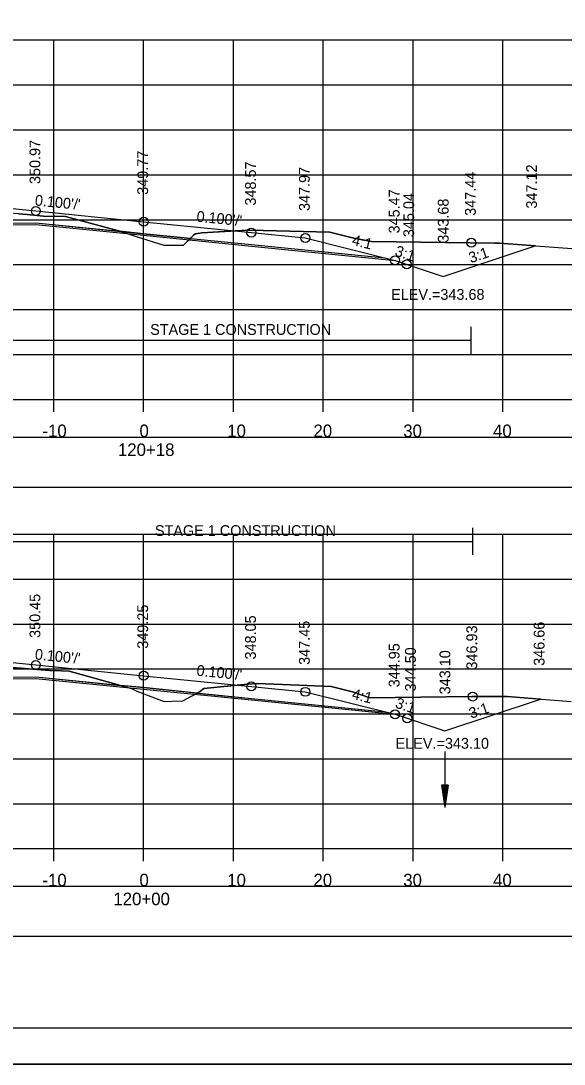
# Model space of a CAD drawing. Extents: x 1376273 to 1384221, y 378927 to 384592.
# Drawn here: x 1377044.1 to 1377104.6, y 380325.2 to 380441.3 of the extents above; entities that cross this region are included whole.
import ezdxf

# ---------------------------------------------------------------- set-up
doc = ezdxf.new("R2010")
doc.units = 0
for name, color, linetype in [('R_Alt Surface', 7, 'Continuous'), ('R_Axis', 7, 'Continuous'), ('R_Axis Annot', 7, 'Continuous'), ('R_Border', 7, 'Continuous'), ('R_Border Notes', 7, 'Continuous'), ('R_Dimension', 7, 'Continuous'), ('R_Exist Surface', 7, 'Continuous'), ('R_Fin Surface', 7, 'Continuous'), ('R_Grid', 7, 'Continuous'), ('R_No Plot', 7, 'Continuous'), ('R_Water', 7, 'Continuous'), ('R_Xsect Elev', 7, 'Continuous'), ('R_Xsect Slope', 7, 'Continuous'), ('T_Detection Zones', 7, 'Continuous')]:
    doc.layers.add(name, color=color, linetype=linetype)

msp = doc.modelspace()

# ---------------------------------------------------------------- linework, layer by layer
at = {"layer": 'R_Alt Surface'}
for points in [[(1377031.48, 380418.66), (1377045.77, 380418.8), (1377057.77, 380417.6), (1377069.77, 380416.4), (1377084.63, 380414.91)], [(1377031.48, 380368.13), (1377045.77, 380368.28), (1377057.77, 380367.08), (1377069.77, 380365.88), (1377084.63, 380364.39)]]:
    msp.add_lwpolyline(points, dxfattribs=at)
at = {"layer": 'R_Axis'}
for p, q in [((1376907.77, 380399.16), (1377207.77, 380399.16)), ((1377047.77, 380397.76), (1377047.77, 380399.16)), ((1377057.77, 380397.76), (1377057.77, 380399.16)), ((1377067.77, 380397.76), (1377067.77, 380399.16)), ((1377077.77, 380397.76), (1377077.77, 380399.16)), ((1377087.77, 380397.76), (1377087.77, 380399.16)), ((1377097.77, 380397.76), (1377097.77, 380399.16)), ((1376907.77, 380349.16), (1377207.77, 380349.16)), ((1377047.77, 380347.76), (1377047.77, 380349.16)), ((1377057.77, 380347.76), (1377057.77, 380349.16)), ((1377067.77, 380347.76), (1377067.77, 380349.16)), ((1377077.77, 380347.76), (1377077.77, 380349.16)), ((1377087.77, 380347.76), (1377087.77, 380349.16)), ((1377097.77, 380347.76), (1377097.77, 380349.16))]:
    msp.add_line(p, q, dxfattribs=at)
at = {"layer": 'R_Axis Annot'}
for points in [[(1376907.2, 380389.4), (1377209.01, 380389.4), (1377209.01, 380394.92), (1376907.2, 380394.92)], [(1376907.2, 380339.4), (1377209.01, 380339.4), (1377209.01, 380344.93), (1376907.2, 380344.93)]]:
    msp.add_lwpolyline(points, close=True, dxfattribs=at)
at = {"layer": 'R_Border'}
msp.add_line((1377215.95, 380329.16), (1376899.77, 380329.16), dxfattribs=at)
at = {"layer": 'R_Dimension'}
for p, q in [((1377094.26, 380404.24), (1377094.26, 380407.24)), ((1377000.91, 380405.74), (1377094.26, 380405.74)), ((1377094.41, 380381.86), (1377094.41, 380384.86)), ((1377001.54, 380383.36), (1377094.41, 380383.36))]:
    msp.add_line(p, q, dxfattribs=at)
at = {"layer": 'R_Exist Surface'}
for points in [[(1377043.83, 380419.81), (1377044.82, 380419.72), (1377047.01, 380419.53), (1377047.87, 380419.54), (1377049.06, 380419.53), (1377054.14, 380418.14), (1377055.82, 380417.67), (1377057.06, 380417.24), (1377060.04, 380416.31), (1377061.51, 380416.33), (1377062.23, 380416.31), (1377063.35, 380417.47), (1377063.56, 380417.6), (1377064.24, 380417.68), (1377069.39, 380418), (1377069.54, 380418.01), (1377069.59, 380418.01), (1377078.52, 380417.78), (1377081.16, 380417.1), (1377083.13, 380416.75), (1377096.88, 380416.56), (1377097.08, 380416.56), (1377097.41, 380416.53), (1377122.09, 380414.74)], [(1377038.09, 380369.71), (1377044.15, 380369.23), (1377045.87, 380369.08), (1377047.3, 380368.97), (1377048.63, 380368.95), (1377049.48, 380368.92), (1377055.07, 380367.37), (1377056.43, 380366.99), (1377057.03, 380366.7), (1377060.05, 380365.54), (1377060.96, 380365.59), (1377062.13, 380365.6), (1377063.99, 380366.61), (1377064.47, 380367), (1377068.95, 380367.43), (1377070.36, 380367.53), (1377073.25, 380367.44), (1377078.66, 380367.21), (1377081.04, 380366.61), (1377082.96, 380365.95), (1377094.33, 380366.09), (1377098.25, 380366.08), (1377105.38, 380365.55)]]:
    msp.add_lwpolyline(points, dxfattribs=at)
at = {"layer": 'R_Fin Surface'}
for points in [[(1377000.91, 380418.81), (1377029.77, 380418.23), (1377030.77, 380418.48), (1377039.77, 380420.73), (1377045.77, 380420.13), (1377057.77, 380418.93), (1377069.77, 380417.73), (1377075.77, 380417.13), (1377085.77, 380414.63), (1377091.13, 380412.84), (1377101.35, 380416.25)], [(1377001.54, 380368.27), (1377029.77, 380367.71), (1377030.77, 380367.96), (1377039.77, 380370.21), (1377045.77, 380369.61), (1377057.77, 380368.41), (1377069.77, 380367.21), (1377075.77, 380366.61), (1377085.77, 380364.11), (1377091.32, 380362.26), (1377101.96, 380365.8)]]:
    msp.add_lwpolyline(points, dxfattribs=at)
at = {"layer": 'R_Grid'}
for p, q in [((1376907.77, 380439.16), (1377207.77, 380439.16)), ((1376907.77, 380439.16), (1377207.77, 380439.16)), ((1377047.77, 380399.16), (1377047.77, 380439.16)), ((1377047.77, 380399.16), (1377047.77, 380439.16)), ((1377057.77, 380399.16), (1377057.77, 380439.16)), ((1377057.77, 380399.16), (1377057.77, 380439.16)), ((1377067.77, 380399.16), (1377067.77, 380439.16)), ((1377067.77, 380399.16), (1377067.77, 380439.16)), ((1377077.77, 380399.16), (1377077.77, 380439.16)), ((1377077.77, 380399.16), (1377077.77, 380439.16)), ((1377087.77, 380399.16), (1377087.77, 380439.16)), ((1377087.77, 380399.16), (1377087.77, 380439.16)), ((1377097.77, 380399.16), (1377097.77, 380439.16)), ((1377097.77, 380399.16), (1377097.77, 380439.16)), ((1376907.77, 380434.16), (1377207.77, 380434.16)), ((1376907.77, 380434.16), (1377207.77, 380434.16)), ((1376907.77, 380429.16), (1377207.77, 380429.16)), ((1376907.77, 380429.16), (1377207.77, 380429.16)), ((1376907.77, 380424.16), (1377207.77, 380424.16)), ((1376907.77, 380424.16), (1377207.77, 380424.16)), ((1376907.77, 380419.16), (1377207.77, 380419.16)), ((1376907.77, 380419.16), (1377207.77, 380419.16)), ((1376907.77, 380414.16), (1377207.77, 380414.16)), ((1376907.77, 380414.16), (1377207.77, 380414.16)), ((1376907.77, 380409.16), (1377207.77, 380409.16)), ((1376907.77, 380409.16), (1377207.77, 380409.16)), ((1376907.77, 380404.16), (1377207.77, 380404.16)), ((1376907.77, 380404.16), (1377207.77, 380404.16)), ((1376907.77, 380399.16), (1377207.77, 380399.16)), ((1376907.77, 380399.16), (1377207.77, 380399.16)), ((1376907.77, 380384.16), (1377207.77, 380384.16)), ((1376907.77, 380384.16), (1377207.77, 380384.16)), ((1377047.77, 380349.16), (1377047.77, 380384.16)), ((1377047.77, 380349.16), (1377047.77, 380384.16)), ((1377057.77, 380349.16), (1377057.77, 380384.16)), ((1377057.77, 380349.16), (1377057.77, 380384.16)), ((1377067.77, 380349.16), (1377067.77, 380384.16)), ((1377067.77, 380349.16), (1377067.77, 380384.16)), ((1377077.77, 380349.16), (1377077.77, 380384.16)), ((1377077.77, 380349.16), (1377077.77, 380384.16)), ((1377087.77, 380349.16), (1377087.77, 380384.16)), ((1377087.77, 380349.16), (1377087.77, 380384.16)), ((1377097.77, 380349.16), (1377097.77, 380384.16)), ((1377097.77, 380349.16), (1377097.77, 380384.16)), ((1376907.77, 380379.16), (1377207.77, 380379.16)), ((1376907.77, 380379.16), (1377207.77, 380379.16)), ((1376907.77, 380374.16), (1377207.77, 380374.16)), ((1376907.77, 380374.16), (1377207.77, 380374.16)), ((1376907.77, 380369.16), (1377207.77, 380369.16)), ((1376907.77, 380369.16), (1377207.77, 380369.16)), ((1376907.77, 380364.16), (1377207.77, 380364.16)), ((1376907.77, 380364.16), (1377207.77, 380364.16)), ((1376907.77, 380359.16), (1377207.77, 380359.16)), ((1376907.77, 380359.16), (1377207.77, 380359.16)), ((1376907.77, 380354.16), (1377207.77, 380354.16)), ((1376907.77, 380354.16), (1377207.77, 380354.16)), ((1376907.77, 380349.16), (1377207.77, 380349.16)), ((1376907.77, 380349.16), (1377207.77, 380349.16))]:
    msp.add_line(p, q, dxfattribs=at)
at = {"layer": 'R_No Plot'}
msp.add_line((1376887.37, 380325.18), (1377220.7, 380325.18), dxfattribs=at)
for points in [[(1376887.36, 380538.51), (1377220.7, 380538.51), (1377220.7, 380325.17), (1376887.36, 380325.17)], [(1377133.69, 380534.62), (1377133.69, 380524.74), (1377169.42, 380524.74), (1377169.42, 380521.82), (1377192.62, 380521.82), (1377192.62, 380497.48), (1377215.95, 380497.48), (1377215.95, 380329.16), (1376899.77, 380329.16), (1376899.77, 380534.62)]]:
    msp.add_lwpolyline(points, close=True, dxfattribs=at)
for points in [[(1377030.77, 380418.48), (1377045.77, 380418.63), (1377057.77, 380417.43), (1377069.77, 380416.23), (1377085.77, 380414.63)], [(1377030.77, 380367.96), (1377045.77, 380368.11), (1377057.77, 380366.91), (1377069.77, 380365.71), (1377085.77, 380364.11)]]:
    msp.add_lwpolyline(points, dxfattribs=at)
for centre in [(1377045.77, 380420.13), (1377045.77, 380420.13), (1377057.77, 380418.93), (1377057.77, 380418.93), (1377069.77, 380417.73), (1377069.77, 380417.73), (1377075.77, 380417.13), (1377075.77, 380417.13), (1377094.26, 380416.59), (1377094.26, 380416.59), (1377085.77, 380414.63), (1377085.77, 380414.63), (1377087.07, 380414.2), (1377087.07, 380414.2), (1377087.07, 380414.2), (1377087.07, 380414.2), (1377045.77, 380369.61), (1377045.77, 380369.61), (1377057.77, 380368.41), (1377057.77, 380368.41), (1377069.77, 380367.21), (1377069.77, 380367.21), (1377075.77, 380366.61), (1377075.77, 380366.61), (1377094.41, 380366.09), (1377094.41, 380366.09), (1377085.77, 380364.11), (1377085.77, 380364.11), (1377087.12, 380363.66), (1377087.12, 380363.66), (1377087.12, 380363.66), (1377087.12, 380363.66)]:
    msp.add_circle(centre, 0.5, dxfattribs=at)
at = {"layer": 'R_Water'}
for p, q in [((1377091.32, 380359.97), (1377091.32, 380353.72)), ((1377090.94, 380356.22), (1377091.32, 380353.72)), ((1377091.69, 380356.22), (1377090.94, 380356.22)), ((1377091, 380356.22), (1377091.32, 380354.14)), ((1377091.07, 380356.22), (1377091.32, 380354.57)), ((1377091.13, 380356.22), (1377091.32, 380354.99)), ((1377091.19, 380356.22), (1377091.32, 380355.41)), ((1377091.26, 380356.22), (1377091.32, 380355.83)), ((1377091.69, 380356.22), (1377091.32, 380353.72)), ((1377091.44, 380356.22), (1377091.32, 380355.41)), ((1377091.56, 380356.22), (1377091.32, 380354.57)), ((1377091.63, 380356.22), (1377091.32, 380354.14)), ((1377091.5, 380356.22), (1377091.32, 380354.99)), ((1377091.37, 380356.22), (1377091.32, 380355.83))]:
    msp.add_line(p, q, dxfattribs=at)
at = {"layer": 'T_Detection Zones'}
for p, q in [((1377042.83, 380418.77), (1377045.77, 380418.8)), ((1377045.77, 380418.8), (1377055.12, 380417.87)), ((1377057.77, 380417.6), (1377055.12, 380417.87)), ((1377062.98, 380417.08), (1377057.77, 380417.6)), ((1377062.98, 380417.08), (1377069.77, 380416.4)), ((1377069.77, 380416.4), (1377084.63, 380414.91)), ((1377043.15, 380368.25), (1377045.77, 380368.28)), ((1377045.77, 380368.28), (1377055.21, 380367.33)), ((1377057.77, 380367.08), (1377055.21, 380367.33)), ((1377063.75, 380366.48), (1377057.77, 380367.08)), ((1377063.75, 380366.48), (1377069.77, 380365.88)), ((1377069.77, 380365.88), (1377084.63, 380364.39))]:
    msp.add_line(p, q, dxfattribs=at)
for points in [[(1377055.12, 380417.87), (1377054.14, 380418.14), (1377049.06, 380419.53), (1377047.87, 380419.54), (1377047.01, 380419.53), (1377044.82, 380419.72), (1377043.83, 380419.81), (1377042.83, 380419.89)], [(1377101.35, 380416.25), (1377097.41, 380416.53), (1377097.08, 380416.56), (1377096.88, 380416.56), (1377083.13, 380416.75), (1377081.16, 380417.1), (1377078.52, 380417.78), (1377069.59, 380418.01), (1377069.54, 380418.01), (1377069.39, 380418), (1377067.95, 380417.91), (1377064.24, 380417.68), (1377063.56, 380417.6), (1377063.35, 380417.47), (1377062.98, 380417.08)], [(1377055.12, 380417.87), (1377055.82, 380417.67), (1377057.06, 380417.24), (1377060.04, 380416.31), (1377061.51, 380416.33), (1377062.23, 380416.31), (1377062.98, 380417.08)], [(1377084.63, 380414.91), (1377085.77, 380414.63), (1377091.13, 380412.84), (1377101.35, 380416.25)], [(1377055.21, 380367.33), (1377055.07, 380367.37), (1377049.48, 380368.92), (1377048.63, 380368.95), (1377047.3, 380368.97), (1377045.87, 380369.08), (1377044.15, 380369.23), (1377043.15, 380369.31)], [(1377055.21, 380367.33), (1377056.43, 380366.99), (1377057.03, 380366.7), (1377060.05, 380365.54), (1377060.96, 380365.59), (1377062.13, 380365.6), (1377063.75, 380366.48)], [(1377101.96, 380365.8), (1377098.25, 380366.08), (1377094.33, 380366.09), (1377082.96, 380365.95), (1377081.04, 380366.61), (1377078.66, 380367.21), (1377073.25, 380367.44), (1377070.36, 380367.53), (1377068.95, 380367.43), (1377068.2, 380367.36), (1377064.47, 380367), (1377063.99, 380366.61), (1377063.75, 380366.48)], [(1377084.63, 380364.39), (1377085.77, 380364.11), (1377091.32, 380362.26), (1377101.96, 380365.8)]]:
    msp.add_lwpolyline(points, dxfattribs=at)

# ---------------------------------------------------------------- texts
at = {"layer": 'R_Axis Annot'}
for s, p in [('-10', (1377046.5, 380394.96)), ('0', (1377057.31, 380394.96)), ('10', (1377067.08, 380394.96)), ('20', (1377076.68, 380394.96)), ('30', (1377086.68, 380394.96)), ('40', (1377096.68, 380394.96)), ('120+18', (1377054.91, 380392.86)), ('-10', (1377046.5, 380344.96)), ('0', (1377057.31, 380344.96)), ('10', (1377067.08, 380344.96)), ('20', (1377076.68, 380344.96)), ('30', (1377086.68, 380344.96)), ('40', (1377096.68, 380344.96)), ('120+00', (1377054.4, 380342.86))]:
    msp.add_text(s, height=1.4, dxfattribs=at).set_placement(p)
at = {"layer": 'R_Border Notes'}
for s, p in [('ELEV.=343.68', (1377085.33, 380410.24)), ('ELEV.=343.10', (1377085.83, 380360.28))]:
    msp.add_text(s, height=1.2, dxfattribs=at).set_placement(p)
at = {"layer": 'R_Dimension'}
for p in [(1377058.5, 380406.34), (1377059.03, 380383.96)]:
    msp.add_text('STAGE 1 CONSTRUCTION', height=1.2, dxfattribs=at).set_placement(p)
at = {"layer": 'R_No Plot'}
for s, p in [('347.44', (1377094.76, 380419.59)), ('345.04', (1377087.89, 380417.22)), ('346.93', (1377094.91, 380369.09)), ('344.50', (1377088.08, 380366.66))]:
    msp.add_text(s, height=1.2, rotation=90, dxfattribs=at).set_placement(p)
at = {"layer": 'R_Xsect Elev'}
for s, p in [('350.97', (1377046.27, 380423.13)), ('349.77', (1377058.27, 380421.93)), ('348.57', (1377070.27, 380420.73)), ('347.97', (1377076.27, 380420.13)), ('347.12', (1377101.57, 380420.4)), ('345.47', (1377086.27, 380417.63)), ('343.68', (1377091.73, 380416.6)), ('350.45', (1377046.27, 380372.61)), ('349.25', (1377058.27, 380371.41)), ('348.05', (1377070.27, 380370.21)), ('347.45', (1377076.27, 380369.61)), ('346.66', (1377102.41, 380369.51)), ('344.95', (1377086.27, 380367.11)), ('343.10', (1377091.92, 380366.33))]:
    msp.add_text(s, height=1.2, rotation=90, dxfattribs=at).set_placement(p)
at = {"layer": 'R_Xsect Slope'}
for s, rotation, p in [("0.100'/'", 354.2894, (1377045.62, 380420.75)), ("0.100'/'", 354.2894, (1377063.62, 380418.95)), ('4:1', 345.9638, (1377080.89, 380416.37)), ('3:1', 341.5651, (1377085.66, 380415.19)), ('3:1', 18.4349, (1377094.2, 380414.31)), ("0.100'/'", 354.2894, (1377045.62, 380370.22)), ("0.100'/'", 354.2894, (1377063.62, 380368.42)), ('4:1', 345.9638, (1377080.89, 380365.84)), ('3:1', 341.5651, (1377085.7, 380364.88)), ('3:1', 18.4349, (1377094.23, 380363.61))]:
    msp.add_text(s, height=1.2, rotation=rotation, dxfattribs=at).set_placement(p)

doc.saveas('drawing.dxf')
